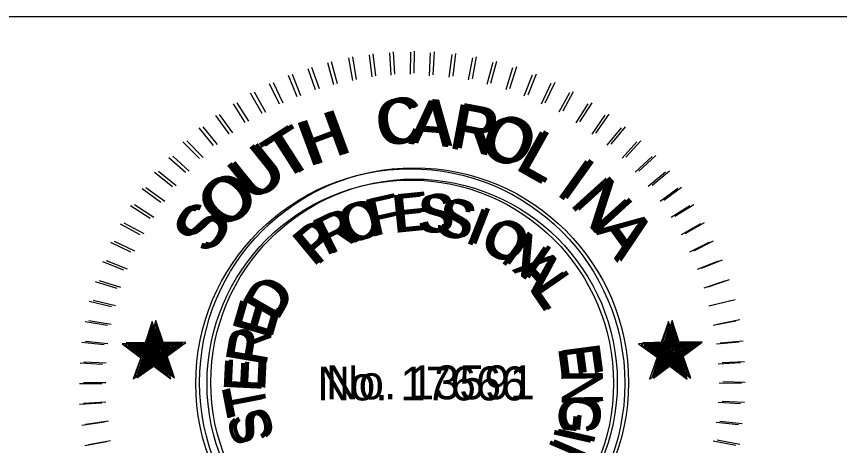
# Model space of a CAD drawing. Extents: x -16 to 5016, y -5 to 5003.
# Drawn here: x 26.289 to 28.397, y -1.099 to 0 of the extents above; entities that cross this region are included whole.
import ezdxf

# ---------------------------------------------------------------- set-up
doc = ezdxf.new("R2010")
doc.units = 0
for name, color, linetype in [('RD_SHT_SEAL_DR', 7, 'Continuous'), ('RD_SHT_SEAL_MA', 7, 'Continuous'), ('RD_SHT_TX', 7, 'Continuous')]:
    doc.layers.add(name, color=color, linetype=linetype)

msp = doc.modelspace()

# ---------------------------------------------------------------- linework, layer by layer
at = {"layer": 'RD_SHT_SEAL_DR'}
for p, q in [((27.1492, -0.1032), (27.159, -0.1615)), ((27.2021, -0.0956), (27.2086, -0.1518)), ((27.254, -0.0902), (27.2572, -0.1474)), ((27.308, -0.0891), (27.307, -0.1452)), ((27.3588, -0.0902), (27.3555, -0.1496)), ((27.4139, -0.0946), (27.4063, -0.1528)), ((27.4668, -0.1032), (27.456, -0.1593)), ((27.0952, -0.115), (27.1104, -0.1712)), ((27.5186, -0.115), (27.5035, -0.1712)), ((26.9948, -0.1474), (27.0164, -0.2026)), ((27.0445, -0.1302), (27.064, -0.1842)), ((27.5694, -0.1291), (27.552, -0.1852)), ((27.6201, -0.1474), (27.5985, -0.2014)), ((26.9462, -0.1691), (26.971, -0.2209)), ((27.6676, -0.1691), (27.6428, -0.2219)), ((26.8976, -0.1927), (26.9268, -0.2447)), ((27.7152, -0.1927), (27.6882, -0.2425)), ((26.8533, -0.2209), (26.8835, -0.2684)), ((27.7627, -0.2209), (27.7314, -0.2695)), ((26.808, -0.2511), (26.8425, -0.2976)), ((27.806, -0.2501), (27.7725, -0.2987)), ((26.7659, -0.2825), (26.8025, -0.3278)), ((27.848, -0.2824), (27.8113, -0.3267)), ((26.7248, -0.3181), (26.7669, -0.3612)), ((27.888, -0.3181), (27.8501, -0.3602)), ((26.6892, -0.3581), (26.7313, -0.3958)), ((27.9268, -0.3558), (27.8836, -0.3958)), ((26.6525, -0.3958), (26.6979, -0.4326)), ((27.9615, -0.3958), (27.9171, -0.4326)), ((26.62, -0.438), (26.6686, -0.4726)), ((27.9927, -0.438), (27.9474, -0.4715)), ((26.5909, -0.4812), (26.6405, -0.5136)), ((28.024, -0.4822), (27.9755, -0.5125)), ((26.5639, -0.5287), (26.6146, -0.5557)), ((28.051, -0.5287), (28.0014, -0.5567)), ((26.539, -0.5751), (26.5909, -0.6)), ((28.0738, -0.5752), (28.023, -0.601)), ((26.5185, -0.6248), (26.5725, -0.6464)), ((28.0964, -0.6237), (28.0425, -0.6453)), ((28.1148, -0.6745), (28.0597, -0.6928)), ((26.5002, -0.6756), (26.5552, -0.6928)), ((26.485, -0.7263), (26.5423, -0.7404)), ((28.1299, -0.7252), (28.0727, -0.7393)), ((26.4743, -0.7782), (26.5315, -0.7879)), ((28.1418, -0.7771), (28.0835, -0.7889)), ((26.4656, -0.8311), (26.5229, -0.8376)), ((28.1504, -0.8311), (28.092, -0.8365)), ((26.4613, -0.8841), (26.5185, -0.8872)), ((28.1536, -0.884), (28.0964, -0.8872)), ((26.4602, -0.9369), (26.5175, -0.9369)), ((28.1558, -0.9369), (28.0985, -0.9358)), ((26.4602, -0.9899), (26.5175, -0.9866)), ((28.1537, -0.9887), (28.0965, -0.9855)), ((26.4656, -1.0438), (26.524, -1.0352)), ((28.1483, -1.0428), (28.091, -1.0374)), ((26.4732, -1.0957), (26.5294, -1.0859)), ((28.1418, -1.0957), (28.0835, -1.0848))]:
    msp.add_line(p, q, dxfattribs=at)
for points in [[(26.646, -0.7782), (26.6276, -0.8354), (26.5694, -0.8354), (26.6168, -0.8711), (26.5974, -0.9251), (26.647, -0.8905), (26.6935, -0.9251), (26.6751, -0.87), (26.7227, -0.8344), (26.6644, -0.8343)], [(27.969, -0.7782), (27.9495, -0.8343), (27.8923, -0.8354), (27.9398, -0.87), (27.9204, -0.9261), (27.969, -0.8905), (28.0165, -0.9262), (27.997, -0.8699), (28.0456, -0.8343), (27.9863, -0.8342)], [(26.645, -0.7868), (26.6298, -0.8365), (26.5758, -0.8365), (26.618, -0.8689), (26.6028, -0.9197), (26.6449, -0.8872), (26.688, -0.9197), (26.672, -0.8678), (26.7161, -0.8376), (26.6632, -0.8366)], [(26.647, -0.7944), (26.6298, -0.8397), (26.5834, -0.8397), (26.6222, -0.8678), (26.6082, -0.9132), (26.646, -0.8851), (26.6849, -0.9142), (26.6686, -0.8667), (26.7086, -0.8408), (26.661, -0.8397)], [(27.968, -0.7857), (27.9517, -0.8365), (27.8988, -0.8376), (27.943, -0.8699), (27.9269, -0.9197), (27.969, -0.8894), (28.0122, -0.9197), (27.996, -0.8688), (28.0391, -0.8365), (27.9851, -0.8376)], [(27.969, -0.7944), (27.955, -0.8408), (27.9064, -0.8397), (27.9452, -0.8678), (27.9311, -0.9142), (27.969, -0.8851), (28.0079, -0.9132), (27.9928, -0.8688), (28.0316, -0.8387), (27.9841, -0.8397)], [(26.647, -0.802), (26.632, -0.8419), (26.5909, -0.843), (26.6255, -0.8667), (26.6125, -0.9067), (26.6449, -0.8819), (26.6805, -0.9067), (26.6686, -0.8667), (26.701, -0.8408), (26.659, -0.8429)], [(26.646, -0.8095), (26.6351, -0.8441), (26.5984, -0.8452), (26.6276, -0.8657), (26.6158, -0.9012), (26.646, -0.8786), (26.6762, -0.9012), (26.6644, -0.8657), (26.6925, -0.8441), (26.659, -0.844)], [(26.646, -0.817), (26.6373, -0.8473), (26.606, -0.8462), (26.6309, -0.8646), (26.6211, -0.8937), (26.647, -0.8754), (26.6719, -0.8948), (26.6611, -0.8646), (26.687, -0.8484), (26.6557, -0.8473)], [(27.968, -0.8019), (27.956, -0.843), (27.9139, -0.843), (27.9495, -0.8667), (27.9333, -0.9057), (27.969, -0.8818), (28.0025, -0.9056), (27.9895, -0.8667), (28.024, -0.8419), (27.982, -0.8419)], [(27.9679, -0.8106), (27.9571, -0.8452), (27.9204, -0.844), (27.9495, -0.8646), (27.9398, -0.9013), (27.9679, -0.8797), (27.997, -0.9002), (27.9873, -0.8667), (28.0175, -0.8452), (27.9798, -0.8441)], [(27.97, -0.8182), (27.9593, -0.8462), (27.928, -0.8462), (27.9539, -0.8635), (27.943, -0.8948), (27.969, -0.8764), (27.9927, -0.8937), (27.9852, -0.8656), (28.0079, -0.8472), (27.9787, -0.8462)], [(26.646, -0.8257), (26.6384, -0.8483), (26.6135, -0.8517), (26.6341, -0.8635), (26.6265, -0.8872), (26.6449, -0.8732), (26.6675, -0.8883), (26.66, -0.8635), (26.6784, -0.8494), (26.6535, -0.8494)], [(26.646, -0.8333), (26.6406, -0.8516), (26.6211, -0.8517), (26.6374, -0.8624), (26.6309, -0.8807), (26.646, -0.871), (26.6622, -0.8818), (26.6568, -0.8635), (26.6719, -0.8527), (26.6514, -0.8506)], [(26.646, -0.8419), (26.6416, -0.8537), (26.6276, -0.8537), (26.6384, -0.8624), (26.6363, -0.8743), (26.647, -0.8667), (26.6557, -0.8754), (26.6535, -0.8624), (26.6644, -0.8548), (26.6503, -0.8537)], [(27.969, -0.8257), (27.9603, -0.8484), (27.9355, -0.8494), (27.957, -0.8646), (27.9485, -0.8873), (27.969, -0.8722), (27.9884, -0.8883), (27.9808, -0.8635), (28.0025, -0.8494), (27.9765, -0.8483)], [(27.969, -0.8343), (27.9636, -0.8516), (27.943, -0.8516), (27.9592, -0.8635), (27.9528, -0.8807), (27.969, -0.8711), (27.9841, -0.8818), (27.9787, -0.8635), (27.9928, -0.8517), (27.9744, -0.8516)], [(27.969, -0.8408), (27.9625, -0.8538), (27.9517, -0.8548), (27.9614, -0.8613), (27.957, -0.8743), (27.969, -0.8678), (27.9798, -0.8754), (27.9755, -0.8635), (27.9874, -0.8548), (27.9744, -0.8537)], [(26.647, -0.8483), (26.6427, -0.8559), (26.6362, -0.8559), (26.6427, -0.8614), (26.6395, -0.8689), (26.647, -0.8635), (26.6514, -0.8689), (26.6493, -0.8602), (26.6557, -0.8571), (26.6492, -0.857)], [(26.647, -0.8571), (26.646, -0.8602), (26.6417, -0.8592), (26.6449, -0.8592), (26.6439, -0.8624), (26.646, -0.8624), (26.6471, -0.8624), (26.647, -0.8602), (26.6503, -0.8581), (26.647, -0.8581)], [(27.968, -0.8483), (27.9669, -0.8559), (27.9581, -0.856), (27.9657, -0.8613), (27.9615, -0.8689), (27.97, -0.8646), (27.9755, -0.8689), (27.9722, -0.8624), (27.9798, -0.856), (27.9722, -0.8571)], [(27.97, -0.857), (27.969, -0.8592), (27.9657, -0.8592), (27.9668, -0.8602), (27.9669, -0.8635), (27.968, -0.8613), (27.9712, -0.8613), (27.97, -0.8602), (27.9711, -0.8592), (27.969, -0.8602)]]:
    msp.add_lwpolyline(points, close=True, dxfattribs=at)
for radius in [0.5496, 0.5207]:
    msp.add_circle((27.3074, -0.9369), radius, dxfattribs=at)
at = {"layer": 'RD_SHT_SEAL_MA'}
for p, q in [((27.1924, -0.0983), (27.1988, -0.1544)), ((27.2443, -0.0928), (27.2475, -0.1501)), ((27.2983, -0.0918), (27.2972, -0.1479)), ((27.349, -0.0928), (27.3458, -0.1523)), ((27.4041, -0.0972), (27.3965, -0.1555)), ((27.0855, -0.1177), (27.1006, -0.1738)), ((27.1395, -0.1058), (27.1492, -0.1641)), ((27.457, -0.1058), (27.4462, -0.162)), ((27.5088, -0.1177), (27.4938, -0.1738)), ((27.0348, -0.1328), (27.0542, -0.1868)), ((27.5596, -0.1318), (27.5423, -0.1879)), ((26.985, -0.1501), (27.0067, -0.2052)), ((27.6103, -0.1501), (27.5888, -0.2041)), ((26.9364, -0.1717), (26.9613, -0.2235)), ((27.6578, -0.1717), (27.633, -0.2246)), ((26.8878, -0.1954), (26.917, -0.2473)), ((27.7054, -0.1954), (27.6784, -0.2451)), ((26.8436, -0.2235), (26.8738, -0.2711)), ((27.7529, -0.2235), (27.7216, -0.2721)), ((27.7961, -0.2527), (27.7627, -0.3013)), ((26.7982, -0.2538), (26.8328, -0.3002)), ((26.7561, -0.2851), (26.7928, -0.3304)), ((27.8383, -0.2851), (27.8015, -0.3293)), ((26.715, -0.3208), (26.7572, -0.3639)), ((27.8782, -0.3208), (27.8404, -0.3628)), ((26.6794, -0.3607), (26.7215, -0.3985)), ((27.9171, -0.3585), (27.8738, -0.3985)), ((26.6427, -0.3985), (26.688, -0.4352)), ((27.9517, -0.3985), (27.9073, -0.4352)), ((26.6103, -0.4406), (26.6588, -0.4752)), ((27.9829, -0.4406), (27.9376, -0.4741)), ((26.5811, -0.4838), (26.6308, -0.5162)), ((28.0143, -0.4849), (27.9657, -0.5151)), ((26.5541, -0.5313), (26.6048, -0.5583)), ((28.0413, -0.5313), (27.9916, -0.5594)), ((26.5293, -0.5778), (26.5811, -0.6026)), ((28.0639, -0.5778), (28.0132, -0.6037)), ((26.5088, -0.6274), (26.5628, -0.6491)), ((28.0867, -0.6263), (28.0327, -0.648)), ((26.4904, -0.6782), (26.5455, -0.6955)), ((28.105, -0.6771), (28.0499, -0.6955)), ((26.4753, -0.729), (26.5325, -0.743)), ((28.1201, -0.7279), (28.0628, -0.7419)), ((28.132, -0.7798), (28.0737, -0.7916)), ((26.4645, -0.7808), (26.5218, -0.7905)), ((26.4558, -0.8338), (26.5131, -0.8402)), ((28.1407, -0.8338), (28.0823, -0.8391)), ((26.4515, -0.8867), (26.5088, -0.8899)), ((28.1438, -0.8867), (28.0867, -0.8899)), ((26.4504, -0.9396), (26.5077, -0.9396)), ((28.146, -0.9396), (28.0888, -0.9385)), ((26.4504, -0.9925), (26.5077, -0.9893)), ((28.1438, -0.9914), (28.0867, -0.9882)), ((26.4558, -1.0465), (26.5142, -1.0378)), ((28.1385, -1.0454), (28.0813, -1.04)), ((26.4634, -1.0983), (26.5196, -1.0886)), ((28.132, -1.0983), (28.0737, -1.0875))]:
    msp.add_line(p, q, dxfattribs=at)
for points in [[(26.6362, -0.7808), (26.6178, -0.8381), (26.5595, -0.8381), (26.607, -0.8737), (26.5876, -0.9277), (26.6373, -0.8931), (26.6838, -0.9277), (26.6653, -0.8726), (26.7128, -0.837), (26.6546, -0.837)], [(26.6351, -0.7894), (26.62, -0.8391), (26.566, -0.8391), (26.6081, -0.8715), (26.593, -0.9223), (26.6351, -0.8899), (26.6783, -0.9223), (26.6621, -0.8704), (26.7064, -0.8402), (26.6535, -0.8391)], [(26.6373, -0.797), (26.62, -0.8423), (26.5736, -0.8423), (26.6124, -0.8704), (26.5984, -0.9158), (26.6362, -0.8878), (26.6751, -0.9169), (26.6588, -0.8693), (26.6988, -0.8434), (26.6513, -0.8423)], [(27.9592, -0.7808), (27.9398, -0.837), (27.8825, -0.8381), (27.93, -0.8726), (27.9106, -0.9288), (27.9592, -0.8931), (28.0068, -0.9288), (27.9873, -0.8726), (28.0358, -0.837), (27.9765, -0.837)], [(27.9581, -0.7883), (27.9419, -0.8391), (27.889, -0.8402), (27.9333, -0.8726), (27.9171, -0.9223), (27.9592, -0.8921), (28.0024, -0.9223), (27.9862, -0.8715), (28.0294, -0.8391), (27.9754, -0.8402)], [(27.9592, -0.797), (27.9452, -0.8434), (27.8966, -0.8423), (27.9354, -0.8704), (27.9214, -0.9169), (27.9592, -0.8878), (27.9981, -0.9158), (27.9829, -0.8715), (28.0218, -0.8413), (27.9743, -0.8423)], [(26.6373, -0.8046), (26.6222, -0.8445), (26.5811, -0.8456), (26.6157, -0.8693), (26.6028, -0.9093), (26.6351, -0.8845), (26.6708, -0.9093), (26.6588, -0.8693), (26.6913, -0.8434), (26.6492, -0.8456)], [(26.6362, -0.8121), (26.6254, -0.8467), (26.5887, -0.8478), (26.6178, -0.8683), (26.6059, -0.9039), (26.6362, -0.8813), (26.6664, -0.9039), (26.6546, -0.8683), (26.6827, -0.8467), (26.6492, -0.8467)], [(26.6362, -0.8197), (26.6276, -0.8499), (26.5963, -0.8488), (26.6211, -0.8672), (26.6113, -0.8963), (26.6373, -0.878), (26.6621, -0.8974), (26.6513, -0.8672), (26.6773, -0.851), (26.6459, -0.8499)], [(27.9581, -0.8046), (27.9463, -0.8456), (27.9041, -0.8456), (27.9398, -0.8693), (27.9236, -0.9083), (27.9592, -0.8845), (27.9927, -0.9083), (27.9798, -0.8693), (28.0143, -0.8445), (27.9722, -0.8445)], [(27.9581, -0.8132), (27.9473, -0.8478), (27.9106, -0.8467), (27.9398, -0.8672), (27.93, -0.9039), (27.9581, -0.8823), (27.9873, -0.9028), (27.9776, -0.8693), (28.0078, -0.8478), (27.97, -0.8467)], [(27.9603, -0.8208), (27.9495, -0.8488), (27.9182, -0.8488), (27.9441, -0.8661), (27.9333, -0.8974), (27.9592, -0.8791), (27.9829, -0.8963), (27.9754, -0.8683), (27.9981, -0.8499), (27.9689, -0.8488)], [(26.6362, -0.8283), (26.6287, -0.851), (26.6038, -0.8543), (26.6243, -0.8661), (26.6168, -0.8899), (26.6351, -0.8758), (26.6578, -0.891), (26.6503, -0.8661), (26.6686, -0.8521), (26.6438, -0.8521)], [(26.6362, -0.8359), (26.6308, -0.8543), (26.6113, -0.8543), (26.6276, -0.8651), (26.6211, -0.8834), (26.6362, -0.8737), (26.6524, -0.8845), (26.647, -0.8661), (26.6621, -0.8553), (26.6416, -0.8532)], [(27.9592, -0.8283), (27.9506, -0.851), (27.9258, -0.8521), (27.9473, -0.8672), (27.9387, -0.8899), (27.9592, -0.8748), (27.9787, -0.891), (27.9711, -0.8661), (27.9927, -0.8521), (27.9668, -0.851)], [(27.9592, -0.837), (27.9538, -0.8543), (27.9333, -0.8543), (27.9495, -0.8661), (27.943, -0.8834), (27.9592, -0.8737), (27.9743, -0.8845), (27.9689, -0.8661), (27.9829, -0.8543), (27.9646, -0.8543)], [(27.9592, -0.8434), (27.9528, -0.8564), (27.9419, -0.8575), (27.9517, -0.864), (27.9473, -0.8769), (27.9592, -0.8704), (27.97, -0.878), (27.9657, -0.8661), (27.9776, -0.8575), (27.9646, -0.8564)], [(26.6362, -0.8445), (26.6318, -0.8564), (26.6178, -0.8564), (26.6287, -0.8651), (26.6265, -0.8769), (26.6373, -0.8693), (26.6459, -0.878), (26.6438, -0.8651), (26.6546, -0.8575), (26.6405, -0.8564)], [(26.6373, -0.851), (26.6329, -0.8586), (26.6265, -0.8586), (26.6329, -0.864), (26.6298, -0.8715), (26.6373, -0.8661), (26.6416, -0.8715), (26.6394, -0.8629), (26.6459, -0.8597), (26.6394, -0.8597)], [(26.6373, -0.8597), (26.6362, -0.8629), (26.6318, -0.8618), (26.6351, -0.8618), (26.634, -0.8651), (26.6362, -0.8651), (26.6373, -0.8651), (26.6373, -0.8629), (26.6405, -0.8608), (26.6373, -0.8608)], [(27.9581, -0.851), (27.957, -0.8586), (27.9484, -0.8586), (27.9559, -0.864), (27.9517, -0.8715), (27.9603, -0.8672), (27.9657, -0.8715), (27.9624, -0.8651), (27.97, -0.8586), (27.9624, -0.8597)], [(27.9603, -0.8597), (27.9592, -0.8618), (27.9559, -0.8618), (27.957, -0.8629), (27.957, -0.8661), (27.9581, -0.864), (27.9613, -0.864), (27.9603, -0.8629), (27.9613, -0.8618), (27.9592, -0.8629)]]:
    msp.add_lwpolyline(points, close=True, dxfattribs=at)
for radius in [0.5496, 0.5207]:
    msp.add_circle((27.2976, -0.9395), radius, dxfattribs=at)
at = {"layer": 'RD_SHT_TX'}
msp.add_line((0, 0), (33.5, 0), dxfattribs=at)

# ---------------------------------------------------------------- texts
at = {"layer": 'RD_SHT_SEAL_DR'}
for s, height, rotation, p in [('C', 0.1157, 7.9045, (27.227, -0.3311)), ('A', 0.1157, 355.5041, (27.3026, -0.3235)), ('R', 0.1157, 349.3039, (27.403, -0.3332)), ('H', 0.1157, 20.3049, (27.0478, -0.3829)), ('O', 0.1157, 336.9035, (27.4776, -0.3451)), ('T', 0.1157, 32.7054, (26.9797, -0.4217)), ('L', 0.1157, 330.7033, (27.5726, -0.3862)), ('U', 0.1157, 38.9056, (26.9019, -0.4769)), ('I', 0.1157, 324.5031, (27.6774, -0.4509)), ('O', 0.1157, 45.1058, (26.8318, -0.5492)), ('N', 0.1157, 312.1026, (27.7141, -0.4779)), ('F', 0.0963, 12.5331, (27.205, -0.5626)), ('E', 0.0963, 5.7476, (27.2652, -0.5517)), ('S', 0.0963, 358.962, (27.325, -0.5497)), ('S', 0.1157, 57.5062, (26.7896, -0.6108)), ('O', 0.0963, 19.3187, (27.1431, -0.5839)), ('S', 0.0963, 345.3909, (27.3675, -0.5521)), ('R', 0.0963, 26.1042, (27.0912, -0.6113)), ('I', 0.0963, 338.6054, (27.4446, -0.5745)), ('P', 0.0963, 39.6753, (27.059, -0.6395)), ('O', 0.0963, 331.8198, (27.4808, -0.5902)), ('A', 0.1157, 305.9024, (27.7778, -0.5449)), ('N', 0.0963, 325.0343, (27.5355, -0.6236)), ('A', 0.0963, 311.4632, (27.5677, -0.6462)), ('L', 0.0963, 304.6776, (27.6122, -0.6964)), ('D', 0.0964, 60.0967, (26.958, -0.7814)), ('E', 0.0964, 73.6728, (26.943, -0.8257)), ('R', 0.0964, 80.4609, (26.929, -0.8948)), ('E', 0.0963, 277.5354, (27.686, -0.8442)), ('E', 0.0964, 87.249, (26.9257, -0.9607)), ('No. 13591', 0.08672, 0.0004, (27.0818, -0.9802)), ('N', 0.0963, 270.7499, (27.6945, -0.9037)), ('T', 0.0964, 100.8252, (26.9343, -1.0103)), ('G', 0.0963, 263.9643, (27.6944, -0.9636)), ('S', 0.0964, 107.6133, (26.9527, -1.0762)), ('I', 0.0963, 257.1788, (27.6805, -1.0441)), ('N', 0.0963, 246.8176, (27.6717, -1.073))]:
    msp.add_text(s, height=height, rotation=rotation, dxfattribs=at).set_placement(p)
at = {"layer": 'RD_SHT_SEAL_MA'}
for s, height, rotation, p in [('C', 0.1157, 7.9041, (27.2168, -0.3339)), ('A', 0.1157, 355.5037, (27.2924, -0.3263)), ('R', 0.1157, 349.3034, (27.3928, -0.3361)), ('H', 0.1157, 20.3045, (27.0375, -0.3858)), ('O', 0.1157, 336.903, (27.4673, -0.348)), ('T', 0.1157, 32.7049, (26.9695, -0.4247)), ('L', 0.1157, 330.7028, (27.5624, -0.389)), ('U', 0.1157, 38.9051, (26.8918, -0.4798)), ('I', 0.1157, 324.5026, (27.6672, -0.4538)), ('O', 0.1157, 45.1053, (26.8215, -0.5521)), ('N', 0.1157, 312.1022, (27.7039, -0.4808)), ('F', 0.0963, 12.5327, (27.1948, -0.5655)), ('E', 0.0963, 5.7471, (27.2551, -0.5546)), ('S', 0.0963, 358.9616, (27.3149, -0.5525)), ('S', 0.1157, 57.5057, (26.7794, -0.6137)), ('O', 0.0963, 19.3182, (27.1329, -0.5868)), ('S', 0.0963, 345.3905, (27.3573, -0.555)), ('R', 0.0963, 26.1038, (27.0809, -0.6142)), ('I', 0.0963, 338.6049, (27.4344, -0.5773)), ('O', 0.0963, 331.8194, (27.4706, -0.593)), ('A', 0.1157, 305.902, (27.7676, -0.5478)), ('P', 0.0963, 39.6749, (27.0488, -0.6424)), ('N', 0.0963, 325.0338, (27.5253, -0.6264)), ('A', 0.0963, 311.4627, (27.5576, -0.6492)), ('L', 0.0963, 304.6772, (27.6021, -0.6993)), ('D', 0.0964, 60.0962, (26.9479, -0.7843)), ('E', 0.0964, 73.6724, (26.9328, -0.8286)), ('R', 0.0964, 80.4605, (26.9188, -0.8977)), ('E', 0.0963, 277.535, (27.6758, -0.8471)), ('E', 0.0964, 87.2486, (26.9155, -0.9636)), ('N', 0.0963, 270.7494, (27.6843, -0.9066)), ('T', 0.0964, 100.8247, (26.9242, -1.0133)), ('G', 0.0963, 263.9639, (27.6842, -0.9665)), ('S', 0.0964, 107.6128, (26.9425, -1.0792)), ('I', 0.0963, 257.1783, (27.6703, -1.0469)), ('N', 0.0963, 246.8171, (27.6616, -1.0759))]:
    msp.add_text(s, height=height, rotation=rotation, dxfattribs=at).set_placement(p)
msp.add_text('No. 17666', height=0.08672, dxfattribs=at).set_placement((27.0596, -0.983))

doc.saveas('drawing.dxf')
